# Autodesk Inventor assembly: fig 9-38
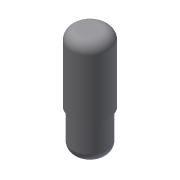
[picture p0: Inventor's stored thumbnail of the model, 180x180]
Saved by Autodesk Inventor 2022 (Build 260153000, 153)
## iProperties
Created: 2013-07
Part Number: fig 9-38
Document SubType Name: Assembly
Designer: CADCIM
Author: CADCIM
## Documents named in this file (3)
- D:\PROJECTS_2021\Resources\Part Files\c09_Inv_2022_prt\fig 9-39.iam
- D:\PROJECTS_2021\Resources\Part Files\c09_Inv_2022_prt\10.ipt
- D:\PROJECTS_2021\Resources\Part Files\c09_Inv_2022_prt\11.ipt
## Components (2 placed, 2 different names)
1. 10:1 — Rigid:1
2. 11:1 — Rigid:1
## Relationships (1: WeldJoint 1)
- Rigid:1 [WeldJoint]: 10:1 ↔ 11:1
